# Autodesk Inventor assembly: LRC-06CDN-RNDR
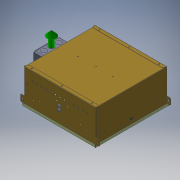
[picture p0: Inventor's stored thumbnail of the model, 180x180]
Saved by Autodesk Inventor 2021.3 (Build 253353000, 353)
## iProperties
Part Number: LRC-06CDN-RNDR
Document SubType Name: Assembly
Designer: JChurch
load_classification: Lighting
motor: 0 ul
Author: JChurch
description: 0:0:Open Appearance 6" Downlight - COB LED
manufacturer: 0:0:The Kirlin Company
model: 0:0:LRC-06CDN
url: 0:0:
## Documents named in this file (7)
- X:\Revit Files\0000-Un-Zipped\COB\LRC-06CDN-RND\LRC-06CDN-RNDR.iam
- X:\INVENTOR\830\830399-00-00.ipt
- X:\INVENTOR\830\830455-00-38.ipt
- X:\INVENTOR\881\881088-00-00.iam
- X:\INVENTOR\KIRLIN_ENG\750\750043-00-XX.iam
- X:\INVENTOR\KIRLIN_ENG\725\725075-00-00.ipt
- X:\Revit Files\0000-Un-Zipped\COB\LRC-06CDN-RND\LRC-06CDN-RNDR_Substitute_1.ipt
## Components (6 placed, 6 different names)
1. 830399-00-00:1 — Mate:2, Mate:3, Mate:6, Tangent:1, Angle:1
2. 830455-00-38:1 — Mate:4, Mate:5, Flush:1, Mate:6, Mate:7, Insert:2
3. 881088-00-00:1 [sub-assembly] — Tangent:1, Mate:7, Angle:1
4. 750043-00-XX:1 [sub-assembly] — Insert:1, Insert:2
5. 725075-00-00:1 — Insert:1
6. LRC-06CDN-RNDR_Substitute_1:1
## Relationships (11: Mate 6, Insert 2, Flush 1, Tangent 1, Angle 1)
- Mate:2: 830399-00-00:1
- Mate:3: 830399-00-00:1
- Mate:4: 830455-00-38:1
- Mate:5: 830455-00-38:1
- Flush:1: 830455-00-38:1
- Mate:6: 830399-00-00:1 ↔ 830455-00-38:1
- Tangent:1: 830399-00-00:1 ↔ 881088-00-00:1
- Mate:7: 830455-00-38:1 ↔ 881088-00-00:1
- Angle:1: 830399-00-00:1 ↔ 881088-00-00:1
- Insert:1: 750043-00-XX:1 ↔ 725075-00-00:1
- Insert:2: 830455-00-38:1 ↔ 750043-00-XX:1
